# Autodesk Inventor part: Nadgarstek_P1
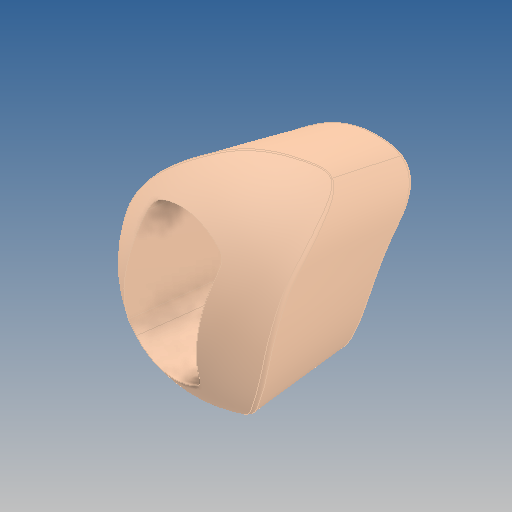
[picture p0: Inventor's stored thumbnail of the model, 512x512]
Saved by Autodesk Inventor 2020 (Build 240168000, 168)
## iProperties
Created: 2019-10
Part Number: Nadgarstek_P1
Material: GFRP
Document SubType Name: Modeling
Designer: yello
Density: 1.75 g/cm^3
Appearance: Default
Author: yello
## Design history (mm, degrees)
feature "Body1"
body "Solid1"
